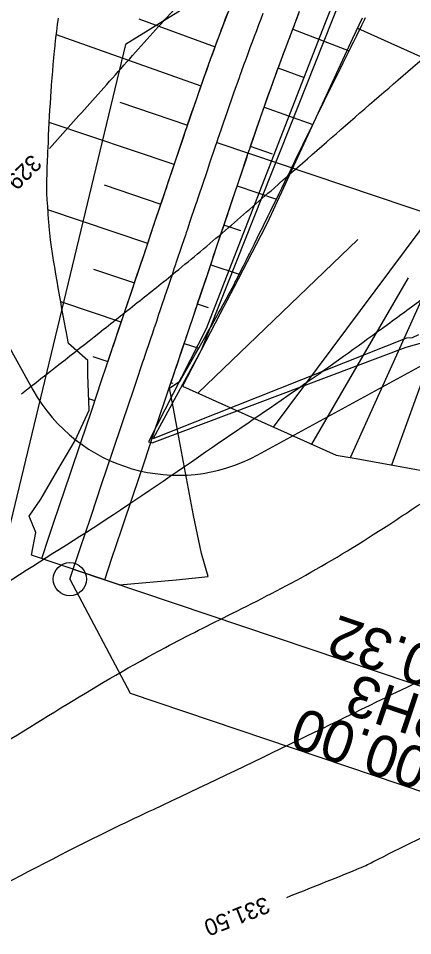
# Model space of a CAD drawing. Extents: x -564043 to -563833, y -1163561 to -1163412.
# Drawn here: x -563904.35 to -563892.49, y -1163520.71 to -1163493.12 of the extents above; entities that cross this region are included whole.
import ezdxf

# ---------------------------------------------------------------- set-up
doc = ezdxf.new("R2010")
doc.units = 0
for name, color, linetype in [('5', 7, 'Continuous'), ('_popis staničení PH3', 7, 'Continuous'), ('_popis staničení T3', 7, 'Continuous'), ('Default', 7, 'Continuous'), ('Line', 7, 'Continuous'), ('Vrstva 24', 7, 'Continuous'), ('Vrstva 25', 7, 'Continuous'), ('Vrstva 26', 7, 'Continuous')]:
    doc.layers.add(name, color=color, linetype=linetype)

msp = doc.modelspace()

# ---------------------------------------------------------------- linework, layer by layer
for p, q in [((-563890.151, -1163481.173), (-563898.85, -1163503.099)), ((-563898.85, -1163503.099), (-563900.295, -1163505.749))]:
    msp.add_line(p, q)
msp.add_lwpolyline([(-563900.324, -1163505.882), (-563892.678, -1163503.006), (-563888.735, -1163501.906), (-563886.271, -1163502.018), (-563883.536, -1163500.684), (-563878.095, -1163497.234), (-563876.621, -1163489.849), (-563880.163, -1163485.998), (-563881.977, -1163484.515), (-563883.765, -1163483.269), (-563890.133, -1163481.092), (-563891.974, -1163485.382), (-563895.143, -1163493.304), (-563898.704, -1163502.458), (-563900.439, -1163505.855)], close=True)
for points in [[(-563901.709, -1163503.594), (-563901.519, -1163503.03), (-563901.312, -1163502.416), (-563901.2, -1163502.083), (-563900.88, -1163501.135), (-563900.561, -1163500.187), (-563900.242, -1163499.24), (-563899.923, -1163498.292), (-563899.604, -1163497.344), (-563899.329, -1163496.528), (-563899.284, -1163496.395), (-563898.956, -1163495.44), (-563898.618, -1163494.488), (-563898.566, -1163494.344), (-563898.27, -1163493.54), (-563897.913, -1163492.595)], [(-563903.651, -1163509.364), (-563903.434, -1163508.717), (-563903.304, -1163508.333), (-563903.114, -1163507.769), (-563902.795, -1163506.821), (-563902.476, -1163505.873), (-563902.157, -1163504.926), (-563901.838, -1163503.978), (-563901.709, -1163503.594), (-563901.613, -1163503.31), (-563901.612, -1163503.306), (-563901.552, -1163503.131), (-563901.519, -1163503.03), (-563901.493, -1163502.955), (-563901.434, -1163502.78), (-563901.375, -1163502.605), (-563901.316, -1163502.429), (-563901.257, -1163502.254), (-563901.2, -1163502.083), (-563901.198, -1163502.079), (-563901.139, -1163501.904), (-563901.08, -1163501.728), (-563901.021, -1163501.553), (-563900.962, -1163501.378), (-563900.903, -1163501.202), (-563900.88, -1163501.135), (-563900.844, -1163501.027), (-563900.785, -1163500.852), (-563900.726, -1163500.676), (-563900.667, -1163500.501), (-563900.608, -1163500.326), (-563900.561, -1163500.187), (-563900.549, -1163500.15), (-563900.49, -1163499.975), (-563900.431, -1163499.8), (-563900.372, -1163499.624), (-563900.313, -1163499.449), (-563900.254, -1163499.274), (-563900.242, -1163499.24), (-563900.194, -1163499.098), (-563900.135, -1163498.923), (-563900.076, -1163498.748), (-563900.017, -1163498.572), (-563899.958, -1163498.397), (-563899.923, -1163498.292), (-563899.899, -1163498.222), (-563899.84, -1163498.046), (-563899.781, -1163497.871), (-563899.722, -1163497.696), (-563899.663, -1163497.52), (-563899.604, -1163497.345), (-563899.604, -1163497.344), (-563899.545, -1163497.17), (-563899.486, -1163496.994), (-563899.427, -1163496.819), (-563899.368, -1163496.644), (-563899.329, -1163496.528), (-563899.309, -1163496.468), (-563899.284, -1163496.395), (-563899.249, -1163496.291), (-563899.188, -1163496.114), (-563899.128, -1163495.937), (-563899.067, -1163495.761), (-563899.006, -1163495.584), (-563898.956, -1163495.44), (-563898.944, -1163495.408), (-563898.882, -1163495.231), (-563898.82, -1163495.055), (-563898.758, -1163494.879), (-563898.695, -1163494.703), (-563898.632, -1163494.527), (-563898.618, -1163494.488), (-563898.568, -1163494.351), (-563898.566, -1163494.344), (-563898.504, -1163494.176), (-563898.44, -1163494), (-563898.376, -1163493.825), (-563898.311, -1163493.65), (-563898.27, -1163493.54), (-563898.246, -1163493.475), (-563898.18, -1163493.3), (-563898.115, -1163493.125), (-563898.048, -1163492.95)], [(-563902.805, -1163509.983), (-563902.486, -1163509.036), (-563902.357, -1163508.652), (-563902.167, -1163508.088), (-563901.848, -1163507.14), (-563901.528, -1163506.193), (-563901.209, -1163505.245), (-563900.89, -1163504.297), (-563900.761, -1163503.913), (-563900.665, -1163503.629), (-563900.664, -1163503.625), (-563900.605, -1163503.45), (-563900.571, -1163503.349), (-563900.546, -1163503.275), (-563900.487, -1163503.099), (-563900.428, -1163502.924), (-563900.369, -1163502.749), (-563900.31, -1163502.573), (-563900.252, -1163502.402), (-563900.251, -1163502.398), (-563900.191, -1163502.223), (-563900.132, -1163502.047), (-563900.073, -1163501.872), (-563900.014, -1163501.697), (-563899.955, -1163501.521), (-563899.933, -1163501.454), (-563899.896, -1163501.346), (-563899.837, -1163501.171), (-563899.778, -1163500.995), (-563899.719, -1163500.82), (-563899.66, -1163500.645), (-563899.613, -1163500.506), (-563899.601, -1163500.469), (-563899.542, -1163500.294), (-563899.483, -1163500.119), (-563899.424, -1163499.943), (-563899.365, -1163499.768), (-563899.306, -1163499.593), (-563899.294, -1163499.559), (-563899.247, -1163499.417), (-563899.188, -1163499.242), (-563899.129, -1163499.067), (-563899.07, -1163498.891), (-563899.011, -1163498.716), (-563898.975, -1163498.611), (-563898.952, -1163498.541), (-563898.893, -1163498.366), (-563898.833, -1163498.19), (-563898.774, -1163498.015), (-563898.715, -1163497.84), (-563898.656, -1163497.664), (-563898.656, -1163497.663), (-563898.597, -1163497.489), (-563898.538, -1163497.314), (-563898.479, -1163497.138), (-563898.42, -1163496.963), (-563898.381, -1163496.847), (-563898.361, -1163496.788), (-563898.337, -1163496.716), (-563898.302, -1163496.612), (-563898.242, -1163496.437), (-563898.182, -1163496.262), (-563898.122, -1163496.087), (-563898.061, -1163495.913), (-563898.012, -1163495.77), (-563898, -1163495.738), (-563897.939, -1163495.563), (-563897.878, -1163495.389), (-563897.816, -1163495.215), (-563897.753, -1163495.04), (-563897.691, -1163494.866), (-563897.677, -1163494.828), (-563897.628, -1163494.692), (-563897.625, -1163494.685), (-563897.565, -1163494.518), (-563897.501, -1163494.345), (-563897.437, -1163494.171), (-563897.373, -1163493.997), (-563897.333, -1163493.889), (-563897.309, -1163493.824), (-563897.244, -1163493.651), (-563897.179, -1163493.478), (-563897.113, -1163493.305), (-563897.048, -1163493.132), (-563896.982, -1163492.959)], [(-563901.756, -1163510.002), (-563901.538, -1163509.355), (-563901.409, -1163508.971), (-563901.219, -1163508.407), (-563900.9, -1163507.459), (-563900.581, -1163506.512), (-563900.262, -1163505.564), (-563899.942, -1163504.616), (-563899.813, -1163504.233), (-563899.717, -1163503.948), (-563899.716, -1163503.944), (-563899.657, -1163503.769), (-563899.623, -1163503.669), (-563899.598, -1163503.594), (-563899.539, -1163503.418), (-563899.48, -1163503.243), (-563899.421, -1163503.068), (-563899.362, -1163502.892), (-563899.304, -1163502.721), (-563899.303, -1163502.717), (-563899.244, -1163502.542), (-563899.185, -1163502.367), (-563899.126, -1163502.191), (-563899.067, -1163502.016), (-563899.008, -1163501.841), (-563898.985, -1163501.773), (-563898.949, -1163501.665), (-563898.89, -1163501.49), (-563898.83, -1163501.315), (-563898.771, -1163501.139), (-563898.712, -1163500.964), (-563898.666, -1163500.826), (-563898.653, -1163500.789), (-563898.594, -1163500.613), (-563898.535, -1163500.438), (-563898.476, -1163500.263), (-563898.417, -1163500.087), (-563898.358, -1163499.912), (-563898.347, -1163499.878), (-563898.299, -1163499.737), (-563898.24, -1163499.561), (-563898.181, -1163499.386), (-563898.122, -1163499.211), (-563898.063, -1163499.035), (-563898.027, -1163498.93), (-563898.004, -1163498.86), (-563897.945, -1163498.685), (-563897.886, -1163498.509), (-563897.827, -1163498.334), (-563897.768, -1163498.159), (-563897.709, -1163497.983), (-563897.708, -1163497.982), (-563897.65, -1163497.808), (-563897.591, -1163497.633), (-563897.532, -1163497.457), (-563897.472, -1163497.282), (-563897.433, -1163497.166), (-563897.414, -1163497.107), (-563897.39, -1163497.036), (-563897.355, -1163496.934), (-563897.296, -1163496.76), (-563897.236, -1163496.587), (-563897.177, -1163496.414), (-563897.117, -1163496.241), (-563897.068, -1163496.1), (-563897.056, -1163496.068), (-563896.996, -1163495.895), (-563896.935, -1163495.723), (-563896.874, -1163495.55), (-563896.812, -1163495.378), (-563896.75, -1163495.205), (-563896.736, -1163495.167), (-563896.688, -1163495.033), (-563896.685, -1163495.026), (-563896.625, -1163494.861), (-563896.562, -1163494.689), (-563896.499, -1163494.517), (-563896.436, -1163494.345), (-563896.396, -1163494.237), (-563896.372, -1163494.173), (-563896.308, -1163494.002), (-563896.243, -1163493.83), (-563896.178, -1163493.659), (-563896.113, -1163493.488), (-563896.048, -1163493.317), (-563896.046, -1163493.311), (-563895.982, -1163493.146), (-563895.916, -1163492.975)], [(-563899.813, -1163504.233), (-563899.623, -1163503.669), (-563899.417, -1163503.055), (-563899.304, -1163502.721), (-563898.985, -1163501.773), (-563898.666, -1163500.826), (-563898.347, -1163499.878), (-563898.027, -1163498.93), (-563897.708, -1163497.982), (-563897.433, -1163497.166), (-563897.39, -1163497.036), (-563897.068, -1163496.1), (-563896.736, -1163495.167), (-563896.685, -1163495.026), (-563896.396, -1163494.237), (-563896.046, -1163493.311), (-563895.888, -1163492.903)], [(-563902.226, -1163504.902), (-563902.261, -1163503.836), (-563902.265, -1163503.407), (-563902.843, -1163502.896), (-563902.843, -1163502.891), (-563902.884, -1163502.682), (-563902.907, -1163502.563), (-563902.924, -1163502.474), (-563902.964, -1163502.265), (-563903.002, -1163502.057), (-563903.041, -1163501.849), (-563903.078, -1163501.641), (-563903.115, -1163501.438), (-563903.115, -1163501.433), (-563903.152, -1163501.226), (-563903.188, -1163501.018), (-563903.223, -1163500.811), (-563903.258, -1163500.604), (-563903.292, -1163500.398), (-563903.305, -1163500.318), (-563903.326, -1163500.191), (-563903.359, -1163499.985), (-563903.391, -1163499.779), (-563903.411, -1163499.577), (-563903.427, -1163499.376), (-563903.439, -1163499.218), (-563903.442, -1163499.176), (-563903.457, -1163498.976), (-563903.471, -1163498.776), (-563903.485, -1163498.576), (-563903.498, -1163498.376), (-563903.499, -1163498.181), (-563903.498, -1163498.143), (-563903.493, -1163497.987), (-563903.488, -1163497.794), (-563903.482, -1163497.601), (-563903.475, -1163497.408), (-563903.468, -1163497.215), (-563903.463, -1163497.1), (-563903.46, -1163497.023), (-563903.451, -1163496.83), (-563903.442, -1163496.638), (-563903.433, -1163496.446), (-563903.423, -1163496.254), (-563903.413, -1163496.062), (-563903.413, -1163496.061), (-563903.402, -1163495.871), (-563903.39, -1163495.68), (-563903.378, -1163495.489), (-563903.365, -1163495.298), (-563903.357, -1163495.171), (-563903.352, -1163495.104), (-563903.345, -1163495.021), (-563903.336, -1163494.903), (-563903.319, -1163494.703), (-563903.302, -1163494.503), (-563903.283, -1163494.303), (-563903.263, -1163494.103), (-563903.246, -1163493.94), (-563903.242, -1163493.904), (-563903.221, -1163493.704), (-563903.198, -1163493.505), (-563903.174, -1163493.306), (-563903.149, -1163493.108)], [(-563899.803, -1163504.236), (-563899.49, -1163504.025), (-563899.488, -1163504.021), (-563899.394, -1163503.858), (-563899.34, -1163503.764), (-563899.3, -1163503.694), (-563899.206, -1163503.531), (-563899.113, -1163503.367), (-563899.019, -1163503.203), (-563898.926, -1163503.039), (-563898.835, -1163502.879), (-563898.833, -1163502.875), (-563898.74, -1163502.711), (-563898.648, -1163502.547), (-563898.555, -1163502.383), (-563898.463, -1163502.219), (-563898.371, -1163502.055), (-563898.336, -1163501.992), (-563898.28, -1163501.89), (-563898.19, -1163501.725), (-563898.1, -1163501.561), (-563898.01, -1163501.396), (-563897.92, -1163501.231), (-563897.853, -1163501.099), (-563897.835, -1163501.064), (-563897.75, -1163500.897), (-563897.666, -1163500.731), (-563897.582, -1163500.564), (-563897.499, -1163500.397), (-563897.415, -1163500.23), (-563897.399, -1163500.197), (-563897.332, -1163500.062), (-563897.249, -1163499.895), (-563897.166, -1163499.728), (-563897.083, -1163499.561), (-563897, -1163499.393), (-563896.951, -1163499.293), (-563896.918, -1163499.226), (-563896.836, -1163499.058), (-563896.754, -1163498.891), (-563896.671, -1163498.723), (-563896.588, -1163498.556), (-563896.506, -1163498.388), (-563896.505, -1163498.388), (-563896.424, -1163498.221), (-563896.342, -1163498.053), (-563896.26, -1163497.886), (-563896.178, -1163497.718), (-563896.124, -1163497.607), (-563896.097, -1163497.552), (-563896.065, -1163497.484), (-563896.018, -1163497.388), (-563895.938, -1163497.224), (-563895.858, -1163497.061), (-563895.779, -1163496.897), (-563895.699, -1163496.734), (-563895.634, -1163496.601), (-563895.619, -1163496.571), (-563895.54, -1163496.408), (-563895.46, -1163496.245), (-563895.38, -1163496.082), (-563895.3, -1163495.919), (-563895.22, -1163495.756), (-563895.202, -1163495.72), (-563895.14, -1163495.594), (-563895.137, -1163495.587), (-563895.06, -1163495.431), (-563894.98, -1163495.269), (-563894.9, -1163495.106), (-563894.82, -1163494.944), (-563894.77, -1163494.842), (-563894.74, -1163494.782), (-563894.66, -1163494.62), (-563894.58, -1163494.458), (-563894.5, -1163494.296), (-563894.42, -1163494.134), (-563894.339, -1163493.972), (-563894.337, -1163493.967), (-563894.259, -1163493.81), (-563894.179, -1163493.649), (-563894.145, -1163493.581), (-563894.099, -1163493.487), (-563894.019, -1163493.325), (-563893.939, -1163493.164), (-563893.904, -1163493.093)], [(-563900.295, -1163505.749), (-563892.658, -1163502.726), (-563892.5, -1163502.714), (-563892.491, -1163502.712), (-563892.306, -1163502.622)], [(-563901.311, -1163510.152), (-563899.601, -1163510.007), (-563898.639, -1163509.904), (-563898.845, -1163509.207), (-563899.079, -1163508.073), (-563899.291, -1163506.946), (-563899.504, -1163505.819), (-563899.717, -1163504.692), (-563899.803, -1163504.236)], [(-563901.311, -1163510.152), (-563903.956, -1163509.261), (-563903.825, -1163508.585), (-563904.027, -1163508.089), (-563903.682, -1163507.578), (-563903.161, -1163506.698), (-563902.64, -1163505.818), (-563902.226, -1163504.902)]]:
    msp.add_lwpolyline(points)
at = {"layer": '5'}
for p, q in [((-563921.324, -1163473.035), (-563903.913, -1163504.291)), ((-563897.15, -1163506.247), (-563862.812, -1163487.513))]:
    msp.add_line(p, q, dxfattribs=at)
msp.add_arc((-563899.545, -1163501.858), 5, 209.1194, 298.6163, dxfattribs=at)
at = {"layer": '_popis staničení PH3'}
for points in [[(-563898.381, -1163496.847), (-563874.436, -1163504.911)], [(-563902.704, -1163509.683), (-563888.488, -1163514.47)], [(-563902.805, -1163509.983), (-563900.986, -1163513.414), (-563889.599, -1163517.249)]]:
    msp.add_lwpolyline(points, dxfattribs=at)
msp.add_circle((-563902.805, -1163509.983), 0.5, dxfattribs=at)
at = {"layer": '_popis staničení T3'}
msp.add_lwpolyline([(-563896.064, -1163490.765), (-563901.13, -1163493.9), (-563906.969, -1163518.117)], dxfattribs=at)
at = {"layer": 'Default'}
msp.add_lwpolyline([(-563894.011, -1163493.107), (-563894.298, -1163493.726), (-563896.807, -1163499.145), (-563896.925, -1163499.399), (-563897.869, -1163501.213), (-563898.286, -1163502.014), (-563899.415, -1163504.184), (-563898.029, -1163504.804), (-563894.792, -1163506.25), (-563894.189, -1163506.359), (-563890.445, -1163507.038), (-563890.304, -1163507.064), (-563887.435, -1163506.214), (-563885.296, -1163505.58), (-563883.769, -1163504.643), (-563881.393, -1163503.187), (-563879.621, -1163502.1), (-563877.447, -1163498.123), (-563877.26, -1163497.64), (-563876.56, -1163495.83), (-563876.213, -1163494.931), (-563876.002, -1163494.387), (-563875.979, -1163493.391), (-563875.957, -1163492.484)], dxfattribs=at)
at = {"layer": 'Line'}
for p, q in [((-563900.732, -1163493.131), (-563898.43, -1163493.976)), ((-563896.095, -1163493.444), (-563894.399, -1163494.092)), ((-563894.152, -1163493.411), (-563889.486, -1163495.501)), ((-563898.853, -1163495.152), (-563903.21, -1163493.612)), ((-563895.74, -1163494.906), (-563896.534, -1163494.614)), ((-563901.301, -1163495.636), (-563899.263, -1163496.333)), ((-563896.958, -1163495.79), (-563895.491, -1163496.309)), ((-563894.356, -1163506.329), (-563889.596, -1163495.749)), ((-563896.67, -1163505.411), (-563889.53, -1163495.82)), ((-563899.662, -1163497.517), (-563903.423, -1163496.25)), ((-563896.702, -1163497.198), (-563897.367, -1163496.971)), ((-563901.77, -1163498.126), (-563900.061, -1163498.702)), ((-563897.767, -1163498.156), (-563896.587, -1163498.553)), ((-563900.46, -1163499.886), (-563903.464, -1163498.875)), ((-563897.655, -1163499.512), (-563898.166, -1163499.34)), ((-563898.953, -1163504.391), (-563894.136, -1163499.765)), ((-563902.088, -1163500.657), (-563900.859, -1163501.071)), ((-563898.565, -1163500.525), (-563897.708, -1163500.813)), ((-563892.627, -1163500.918), (-563895.529, -1163505.921)), ((-563891.196, -1163501.236), (-563893.126, -1163506.552)), ((-563901.258, -1163502.256), (-563903.078, -1163501.643)), ((-563898.633, -1163501.821), (-563898.963, -1163501.709)), ((-563899.362, -1163502.894), (-563898.927, -1163503.041)), ((-563902.117, -1163503.285), (-563901.657, -1163503.44)), ((-563899.698, -1163504.1), (-563899.761, -1163504.079)), ((-563902.056, -1163504.625), (-563902.237, -1163504.564))]:
    msp.add_line(p, q, dxfattribs=at)
at = {"layer": 'Vrstva 24'}
for points in [[(-563903.419, -1163497.029), (-563902.125, -1163495.59), (-563900.744, -1163494.039), (-563899.345, -1163492.505), (-563898.448, -1163491.553), (-563897.897, -1163490.941), (-563897.635, -1163490.622), (-563897.383, -1163490.29), (-563897.001, -1163489.401), (-563896.398, -1163486.71), (-563896.305, -1163486.212), (-563896.276, -1163485.962), (-563896.268, -1163485.713), (-563896.394, -1163485.294), (-563896.666, -1163484.924), (-563897.969, -1163483.548), (-563899.309, -1163482.237), (-563900.743, -1163480.898), (-563903.659, -1163478.289), (-563907.403, -1163474.951), (-563909.511, -1163473.024), (-563914.099, -1163468.742), (-563916.271, -1163466.637)], [(-563905.221, -1163519.388), (-563901.417, -1163517.444), (-563900.291, -1163516.907), (-563895.909, -1163514.815), (-563892.135, -1163512.984), (-563890.63, -1163512.267), (-563888.864, -1163511.357), (-563887.99, -1163510.869), (-563887.125, -1163510.367), (-563886.26, -1163509.866), (-563885.383, -1163509.384), (-563882.362, -1163507.826), (-563880.585, -1163506.938), (-563878.549, -1163505.818), (-563872.848, -1163502.599), (-563870.632, -1163501.288), (-563869.542, -1163500.601), (-563868.575, -1163499.969)]]:
    msp.add_spline(points, degree=3, dxfattribs=at)
at = {"layer": 'Vrstva 25'}
msp.add_spline([(-563905.141, -1163510.37), (-563904.922, -1163510.229), (-563901.706, -1163508.177), (-563898.297, -1163505.868), (-563895.6, -1163504.013), (-563893.249, -1163502.324), (-563892.081, -1163501.469), (-563890.919, -1163500.608), (-563889.757, -1163499.746), (-563888.589, -1163498.892), (-563887.491, -1163498.145), (-563886.364, -1163497.441), (-563885.229, -1163496.747), (-563884.107, -1163496.03), (-563883.48, -1163495.59), (-563883.181, -1163495.349), (-563882.893, -1163495.092), (-563882.209, -1163494.336), (-563881.626, -1163493.502), (-563881.193, -1163492.783), (-563880.36, -1163491.213), (-563880.004, -1163490.417), (-563879.711, -1163489.616), (-563879.829, -1163489.186), (-563884.789, -1163483.345)], degree=3, dxfattribs=at)
at = {"layer": 'Vrstva 26'}
for points in [[(-563904.255, -1163504.408), (-563901.932, -1163502.584), (-563900.774, -1163501.667), (-563899.621, -1163500.744), (-563898.128, -1163499.495), (-563896.658, -1163498.219), (-563892.051, -1163494.217), (-563891.058, -1163493.351), (-563890.3, -1163492.602), (-563889.946, -1163492.201), (-563889.6, -1163491.789), (-563889.274, -1163491.333), (-563889.128, -1163491.092), (-563888.986, -1163490.845), (-563888.757, -1163490.393), (-563888.565, -1163489.929), (-563888.402, -1163489.454), (-563888.258, -1163488.97), (-563888.179, -1163488.634), (-563888.132, -1163488.29), (-563888.126, -1163487.946), (-563888.168, -1163487.609), (-563888.372, -1163487.087), (-563888.888, -1163486.275), (-563889.418, -1163485.493), (-563889.974, -1163484.737), (-563890.569, -1163484.004), (-563892.45, -1163481.915), (-563894.839, -1163479.601), (-563896.896, -1163477.665), (-563897.939, -1163476.713), (-563899, -1163475.779), (-563899.292, -1163475.563), (-563900.233, -1163474.949)], [(-563906.28, -1163515.803), (-563905.884, -1163515.571), (-563902.883, -1163513.741), (-563899.929, -1163512.038), (-563897.928, -1163511.018), (-563895.553, -1163509.778), (-563893.055, -1163508.246), (-563892.353, -1163507.782), (-563891.657, -1163507.311), (-563890.96, -1163506.841), (-563890.257, -1163506.379), (-563888.16, -1163505.094), (-563886.21, -1163504.031), (-563880.965, -1163501.085), (-563878.454, -1163499.578), (-563877.23, -1163498.772), (-563876.032, -1163497.922), (-563874.901, -1163496.941), (-563873.614, -1163495.651), (-563873.276, -1163495.107), (-563873.154, -1163494.587), (-563873.048, -1163494.066), (-563872.865, -1163493.019), (-563872.827, -1163492.778)], [(-563896.274, -1163519.554), (-563894.165, -1163518.707), (-563893.901, -1163518.593), (-563893.686, -1163518.487), (-563888.411, -1163515.922), (-563883.796, -1163513.845), (-563882.856, -1163513.463), (-563881.551, -1163512.898), (-563877.829, -1163511.052), (-563874.459, -1163509.5), (-563873.358, -1163509.055), (-563872.244, -1163508.643), (-563871.128, -1163508.237), (-563870.019, -1163507.811), (-563865.656, -1163505.903), (-563863.431, -1163504.67), (-563862.373, -1163503.951), (-563861.332, -1163503.174), (-563860.403, -1163502.078), (-563859.968, -1163500.761)]]:
    msp.add_spline(points, degree=3, dxfattribs=at)

# ---------------------------------------------------------------- texts
at = {"layer": '_popis staničení PH3'}
for s, p in [('0+000.32', (-563888.089, -1163513.285)), ('ZU PH3 ', (-563888.568, -1163514.707)), ('0+000.00', (-563889.201, -1163516.064))]:
    msp.add_text(s, height=1.25, rotation=161.3882, dxfattribs=at).set_placement(p)
at = {"layer": 'Vrstva 25'}
for s, rotation, p in [('329.00', 224.4524, (-563903.955, -1163497.176)), ('331.50', 201.5654, (-563896.912, -1163519.52))]:
    msp.add_text(s, height=0.5, rotation=rotation, dxfattribs=at).set_placement(p)

doc.saveas('drawing.dxf')
